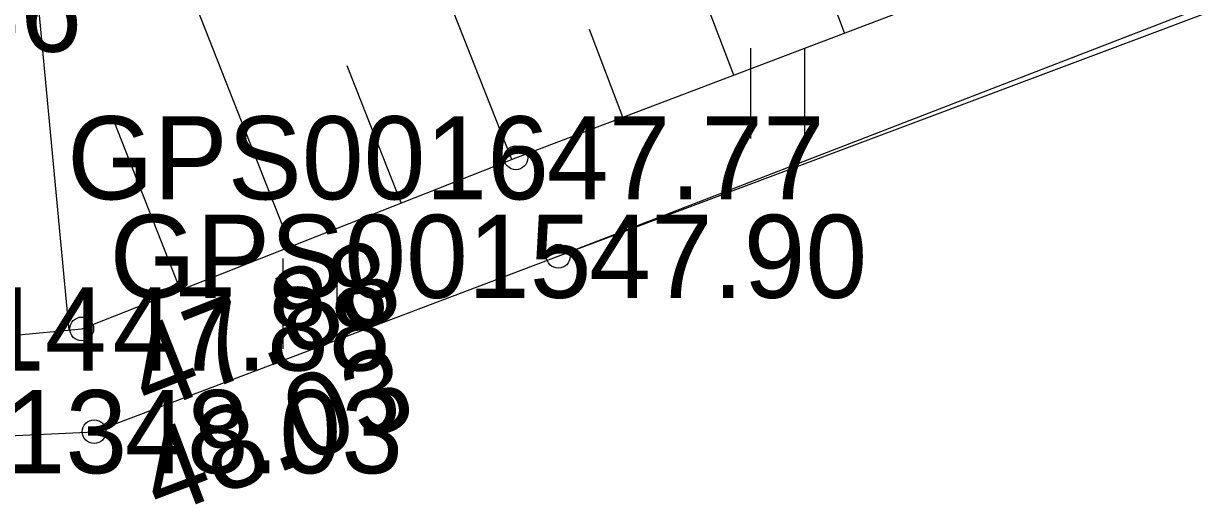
# Model space of a CAD drawing. Extents: x 551623 to 559850, y 6561220 to 6567135.
# Drawn here: x 555073 to 555082.96, y 6565630.69 to 6565634.74 of the extents above; entities that cross this region are included whole.
import ezdxf

# ---------------------------------------------------------------- set-up
doc = ezdxf.new("R2010")
doc.units = 0
for name, color, linetype in [('HALJASTUS', 7, 'Continuous'), ('KORGUS-EH2000', 7, 'Continuous'), ('MOOTKORG-EH2000', 7, 'Continuous'), ('MOOTMPUNKT', 7, 'Continuous'), ('MOOTNR', 7, 'Continuous'), ('MOOTPIIR', 7, 'Continuous'), ('RELJEEF', 7, 'Continuous'), ('TEE', 7, 'Continuous')]:
    doc.layers.add(name, color=color, linetype=linetype)

msp = doc.modelspace()

# ---------------------------------------------------------------- linework, layer by layer
at = {"layer": 'HALJASTUS'}
for p, q in [((555079.1245, 6565634.5306), (555079.1245, 6565633.7695)), ((555079.5796, 6565634.5306), (555079.5796, 6565633.7695)), ((555075.184, 6565632.7598), (555075.184, 6565631.9987)), ((555075.6391, 6565632.7598), (555075.6391, 6565631.9987))]:
    msp.add_line(p, q, dxfattribs=at)
at = {"layer": 'KORGUS-EH2000'}
for centre in [(555073.4899, 6565632.1665), (555073.594, 6565631.3013)]:
    msp.add_circle(centre, 0.1, dxfattribs=at)
at = {"layer": 'MOOTMPUNKT'}
for centre in [(555077.1472, 6565633.6078), (555077.5049, 6565632.7783), (555073.4899, 6565632.1665), (555073.594, 6565631.3013)]:
    msp.add_circle(centre, 0.1, dxfattribs=at)
at = {"layer": 'MOOTPIIR'}
msp.add_lwpolyline([(555050.2439, 6565639.6141), (555053.3585, 6565643.9059), (555058.4298, 6565638.6367), (555062.7058, 6565634.3914), (555065.8288, 6565631.9982), (555069.9868, 6565631.1304), (555073.594, 6565631.3013), (555077.5049, 6565632.7783), (555089.3421, 6565637.2218), (555090.3766, 6565638.4611), (555094.1654, 6565645.8024), (555095.317, 6565648.3277), (555095.66, 6565648.9184), (555092.3318, 6565650.6658), (555085.2081, 6565648.4649), (555080.5888, 6565649.3805), (555070.9545, 6565650.337), (555063.9197, 6565649.7282), (555057.1417, 6565653.1617), (555057.1215, 6565656.6048), (555043.8457, 6565668.2194)], dxfattribs=at)
at = {"layer": 'RELJEEF'}
for p, q in [((555073.3843, 6565632.1566), (555072.8755, 6565637.5661)), ((555075.252, 6565632.8609), (555073.4603, 6565637.4072)), ((555077.1127, 6565633.5942), (555075.8677, 6565636.7534)), ((555078.9824, 6565634.3044), (555078.2997, 6565636.1029)), ((555079.9173, 6565634.6592), (555079.7428, 6565635.1189)), ((555078.0474, 6565633.9495), (555077.7666, 6565634.6893)), ((555076.1823, 6565633.2276), (555075.7268, 6565634.3834)), ((555074.3216, 6565632.4943), (555073.7629, 6565633.9121))]:
    msp.add_line(p, q, dxfattribs=at)
msp.add_lwpolyline([(555033.8936, 6565670.2122), (555034.6142, 6565663.0566), (555035.301, 6565660.3762), (555036.7787, 6565657.7005), (555046.6503, 6565650.9745), (555053.9757, 6565644.6623), (555059.2178, 6565638.9662), (555063.0062, 6565635.0653), (555066.5578, 6565633.2764), (555069.9318, 6565631.8318), (555073.4899, 6565632.1665), (555077.1472, 6565633.6078), (555087.0496, 6565637.3664), (555088.7901, 6565638.5116), (555093.7058, 6565645.8538), (555094.5187, 6565648.167)], dxfattribs=at)
at = {"layer": 'TEE'}
msp.add_lwpolyline([(555020.4731, 6565663.7991), (555033.1636, 6565657.9767), (555034.7314, 6565658.0205), (555036.1614, 6565657.1188), (555036.3144, 6565656.1644), (555045.7181, 6565650.093), (555053.3585, 6565643.9059), (555058.4298, 6565638.6367), (555062.7058, 6565634.3914), (555065.8288, 6565631.9982), (555069.9868, 6565631.1304), (555073.594, 6565631.3013), (555077.5049, 6565632.7783), (555087.2149, 6565636.533), (555089.3421, 6565637.2218), (555090.3766, 6565638.4611), (555094.1654, 6565645.8024), (555095.317, 6565648.3277), (555095.8818, 6565650.0822)], dxfattribs=at)

# ---------------------------------------------------------------- texts
at = {"layer": 'KORGUS-EH2000'}
for s, rotation, p in [(' 47.88', 21.50883, (555073.8107, 6565631.3524)), (' 48.03', 20.68967, (555073.9031, 6565630.4827))]:
    msp.add_text(s, height=0.7, rotation=rotation, dxfattribs=at).set_placement(p)
at = {"layer": 'MOOTKORG-EH2000'}
for s, p in [(' 45.86', (555070.8905, 6565634.5009)), (' 47.77', (555077.1472, 6565633.2578)), (' 47.90', (555077.5049, 6565632.4283)), (' 47.88', (555073.4899, 6565631.8165)), (' 48.03', (555073.594, 6565630.9513))]:
    msp.add_text(s, height=0.7, dxfattribs=at).set_placement(p)
at = {"layer": 'MOOTNR'}
for s, p in [('GPS0016 ', (555073.3674, 6565633.2578)), ('GPS0015 ', (555073.7251, 6565632.4283)), ('GPS0014 ', (555069.6402, 6565631.8165)), ('GPS0013 ', (555069.8142, 6565630.9513))]:
    msp.add_text(s, height=0.7, dxfattribs=at).set_placement(p)

doc.saveas('drawing.dxf')
